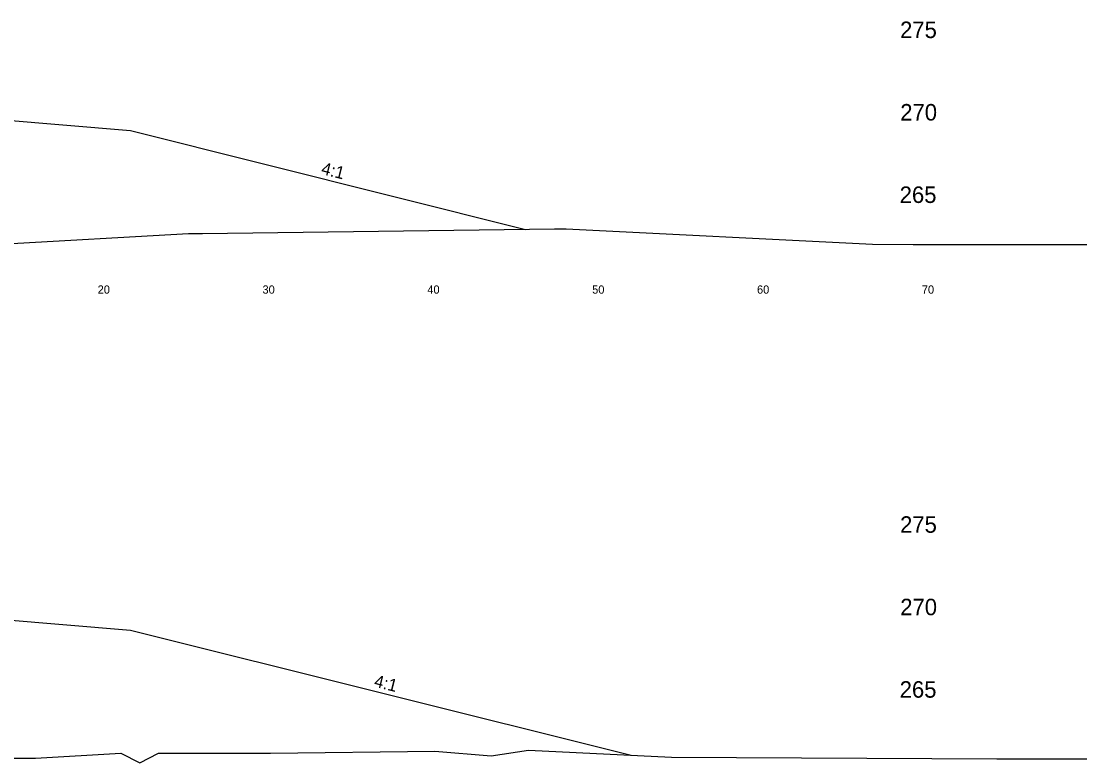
# Model space of a CAD drawing. Extents: x 1000 to 1162, y 999 to 8520.
# Drawn here: x 1095.4 to 1160, y 6651.1 to 6696 of the extents above; entities that cross this region are included whole.
import ezdxf

# ---------------------------------------------------------------- set-up
doc = ezdxf.new("R2010")
doc.units = 0
for name, color, linetype in [('Level 11', 7, 'Continuous'), ('Level 32', 7, 'Continuous'), ('Level 56', 7, 'Continuous'), ('Level 6', 7, 'Continuous'), ('Level 60', 7, 'Continuous'), ('Level 7', 7, 'Continuous')]:
    doc.layers.add(name, color=color, linetype=linetype)

msp = doc.modelspace()

# ---------------------------------------------------------------- linework, layer by layer
at = {"layer": 'Level 6'}
for p, q in [((1094, 6690.054), (1102, 6689.387)), ((1094, 6659.767), (1102, 6659.101))]:
    msp.add_line(p, q, dxfattribs=at)
at = {"layer": 'Level 60'}
for p, q in [((1094.075, 6682.493), (1105.503, 6683.143)), ((1105.503, 6683.143), (1106.354, 6683.144)), ((1106.354, 6683.144), (1127.716, 6683.423)), ((1127.716, 6683.423), (1128.426, 6683.43)), ((1128.426, 6683.43), (1147.006, 6682.501)), ((1147.006, 6682.501), (1149.476, 6682.488)), ((1149.476, 6682.488), (1160, 6682.488)), ((1093.964, 6651.323), (1096.237, 6651.324)), ((1096.237, 6651.324), (1101.414, 6651.626)), ((1101.414, 6651.626), (1102.552, 6651.059)), ((1102.552, 6651.059), (1103.689, 6651.628)), ((1103.689, 6651.628), (1110.491, 6651.632)), ((1110.491, 6651.632), (1120.459, 6651.762)), ((1120.459, 6651.762), (1123.863, 6651.482)), ((1123.863, 6651.482), (1126.128, 6651.823)), ((1126.128, 6651.823), (1134.82, 6651.388)), ((1134.82, 6651.388), (1154.556, 6651.285)), ((1154.556, 6651.285), (1160, 6651.285))]:
    msp.add_line(p, q, dxfattribs=at)
at = {"layer": 'Level 7'}
for p, q in [((1102, 6689.387), (1125.95, 6683.4)), ((1102, 6659.101), (1132.357, 6651.511))]:
    msp.add_line(p, q, dxfattribs=at)

# ---------------------------------------------------------------- texts
at = {"layer": 'Level 11'}
for s, p in [(' 275', (1148.307, 6695)), (' 270', (1148.319, 6690)), (' 265', (1148.284, 6685)), (' 275', (1148.307, 6665)), (' 270', (1148.319, 6660)), (' 265', (1148.284, 6655))]:
    msp.add_text(s, height=1, dxfattribs=at).set_placement(p)
at = {"layer": 'Level 32'}
for p in [(1113.52, 6686.765), (1116.724, 6655.678)]:
    msp.add_text('4:1', height=0.75, rotation=345.96376, dxfattribs=at).set_placement(p)
at = {"layer": 'Level 56'}
for s, p in [('20', (1100, 6679.5)), ('30', (1110, 6679.5)), ('40', (1120, 6679.5)), ('50', (1130, 6679.5)), ('60', (1140, 6679.5)), ('70', (1150, 6679.5))]:
    msp.add_text(s, height=0.5, dxfattribs=at).set_placement(p)

doc.saveas('drawing.dxf')
